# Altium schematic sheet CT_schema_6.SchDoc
size 274 x 160 mm
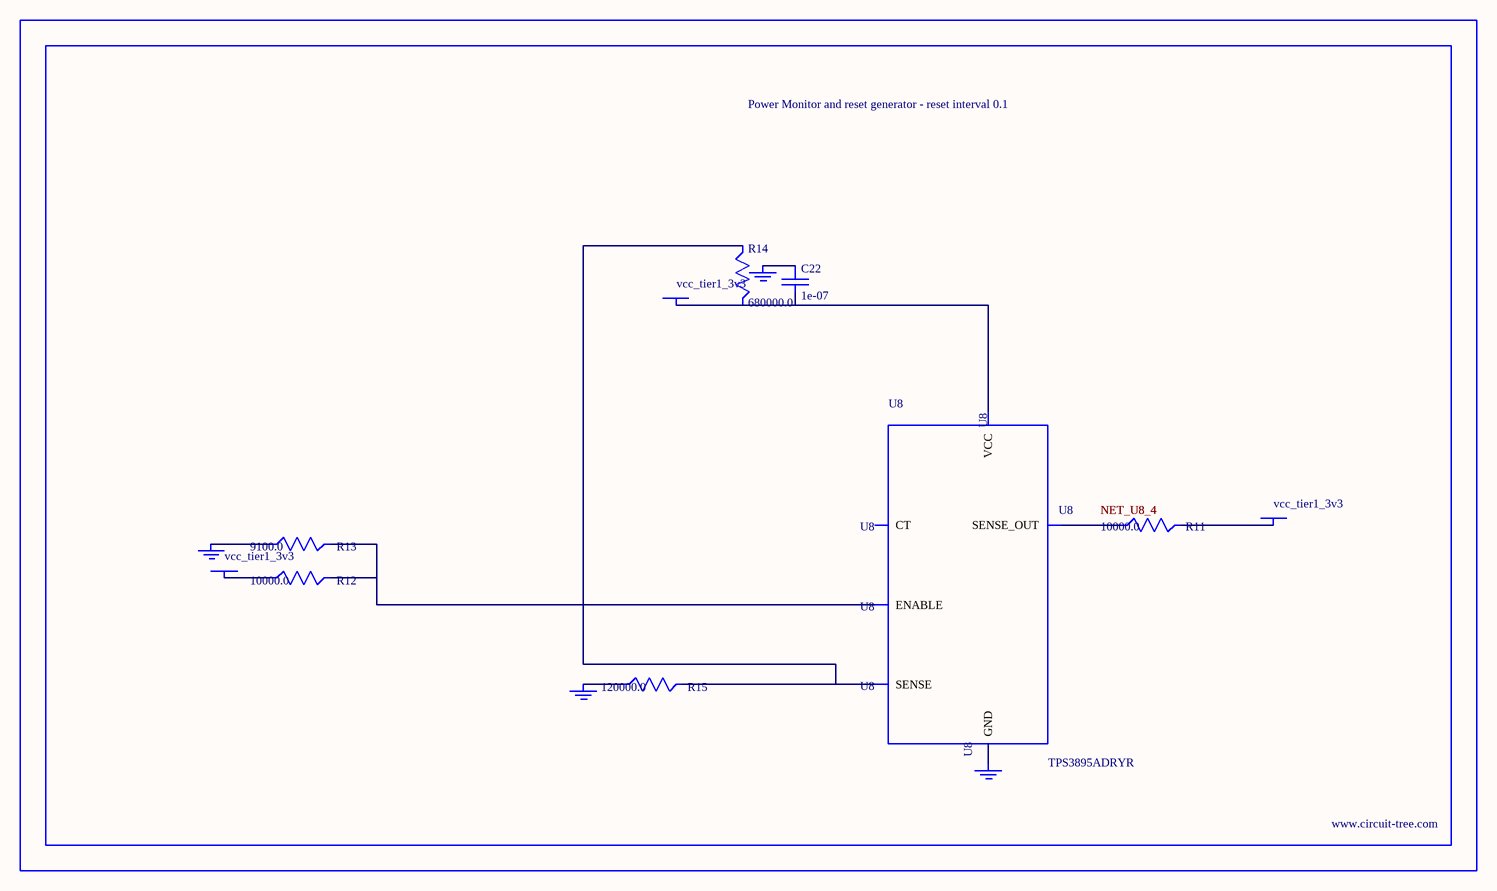
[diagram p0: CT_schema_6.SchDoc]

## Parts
BORDER5  (no value)
C22  1e-07  [C0402]
GND_INSTANCE_5_0  (no value)
GND_INSTANCE_5_1  (no value)
GND_INSTANCE_5_2  (no value)
GND_INSTANCE_5_3  (no value)
POWER_INSTANCE_5_0  vcc_tier1_3v3
POWER_INSTANCE_5_1  vcc_tier1_3v3
POWER_INSTANCE_5_2  vcc_tier1_3v3
R11  10000.0  [R0603]
R12  10000.0  [R0603]
R13  9100.0  [R0603]
R14  680000.0  [R0603]
R15  120000.0  [R0603]
U8  TPS3895ADRYR  [SON-6]

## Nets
NetC22_1: C22.1 GND_INSTANCE_5_2.0(GND)
NetC22_2: C22.2 POWER_INSTANCE_5_2.0(PWR) R14.2 U8.6(VCC)
NetGND_INSTANCE_5_0_0: GND_INSTANCE_5_0.0(GND) R13.1
NetGND_INSTANCE_5_1_0: GND_INSTANCE_5_1.0(GND) R15.1
NetGND_INSTANCE_5_3_0: GND_INSTANCE_5_3.0(GND) U8.2(GND)
NetPOWER_INSTANCE_5_0_0: POWER_INSTANCE_5_0.0(PWR) R12.1
NetPOWER_INSTANCE_5_1_0: POWER_INSTANCE_5_1.0(PWR) R11.2
NetR11_1: R11.1 U8.4(SENSE_OUT)
NetR12_2: R12.2 R13.2 U8.1(ENABLE)
NetR14_1: R14.1 R15.2 U8.3(SENSE)

Not connected (* = marked no-connect by the designer): U8 5(CT)

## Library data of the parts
BORDER5 = BORDER_PAGE5
C22 = C0402C104K3RACTU
GND_INSTANCE_5_0-GND_INSTANCE_5_3 = GND
POWER_INSTANCE_5_0-POWER_INSTANCE_5_2 = PWR
R11 R12 = RC0603JR-0710KL
R13 = RC0603JR-079K1L
R14 = RC0603JR-07680KL
R15 = RC0603JR-07120KL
